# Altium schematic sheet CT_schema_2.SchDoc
size 316 x 185 mm
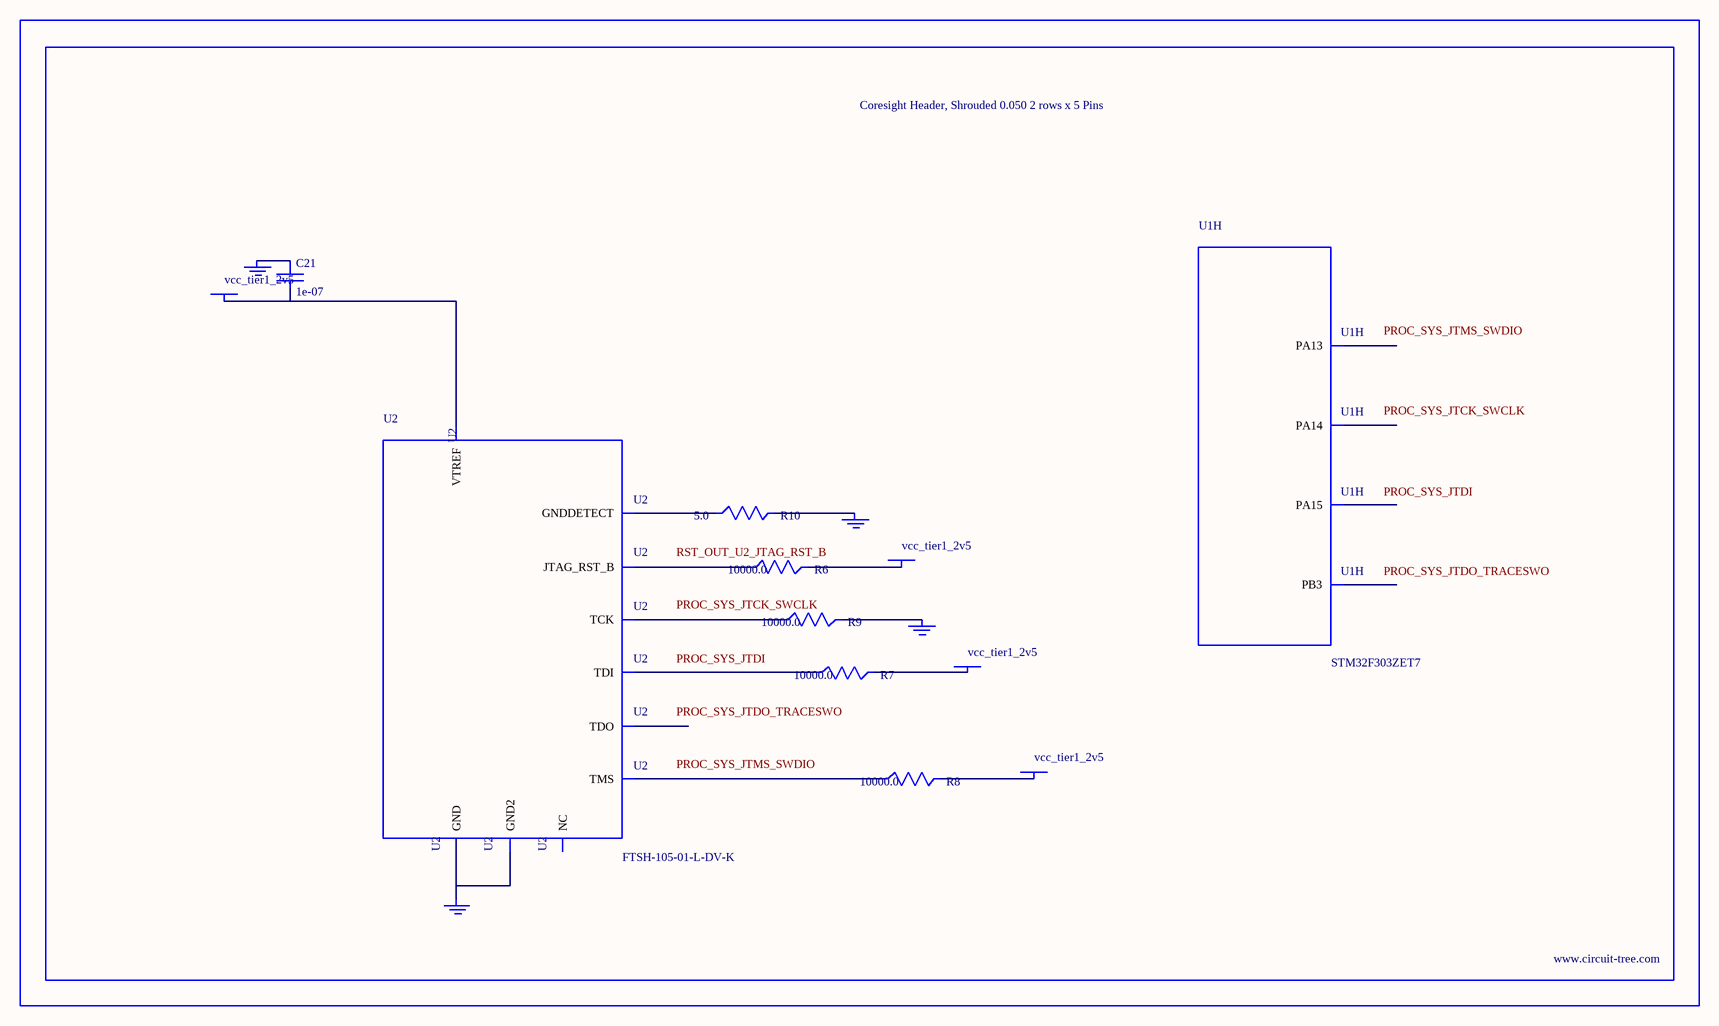
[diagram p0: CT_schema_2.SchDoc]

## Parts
BORDER1  (no value)
C21  1e-07  [C0402]
GND_INSTANCE_1_0  (no value)
GND_INSTANCE_1_1  (no value)
GND_INSTANCE_1_2  (no value)
GND_INSTANCE_1_3  (no value)
POWER_INSTANCE_1_0  vcc_tier1_2v5
POWER_INSTANCE_1_1  vcc_tier1_2v5
POWER_INSTANCE_1_2  vcc_tier1_2v5
POWER_INSTANCE_1_3  vcc_tier1_2v5
R6  10000.0  [R0603]
R7  10000.0  [R0603]
R8  10000.0  [R0603]
R9  10000.0  [R0603]
R10  5.0  [R0603]
U1  STM32F303ZET7  [LQFP144]  (part H of 12)
U2  FTSH-105-01-L-DV-K  [SAMTEC_FTSH-105-01-L-DV-K]

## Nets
NetC21_1: C21.1 GND_INSTANCE_1_0.0(GND)
NetC21_2: C21.2 POWER_INSTANCE_1_0.0(PWR) U2.1(VTREF)
NetGND_INSTANCE_1_1_0: GND_INSTANCE_1_1.0(GND) R9.2
NetGND_INSTANCE_1_2_0: GND_INSTANCE_1_2.0(GND) R10.2
NetGND_INSTANCE_1_3_0: GND_INSTANCE_1_3.0(GND) U2.3(GND) U2.5(GND2)
NetPOWER_INSTANCE_1_1_0: POWER_INSTANCE_1_1.0(PWR) R8.2
NetPOWER_INSTANCE_1_2_0: POWER_INSTANCE_1_2.0(PWR) R7.2
NetPOWER_INSTANCE_1_3_0: POWER_INSTANCE_1_3.0(PWR) R6.2
NetR6_1: R6.1 U2.10(JTAG_RST_B)
NetR7_1: R7.1 U2.8(TDI)
NetR8_1: R8.1 U2.2(TMS)
NetR9_1: R9.1 U2.4(TCK)
NetR10_1: R10.1 U2.9(GNDDETECT)

Not connected (* = marked no-connect by the designer): U1 105(PA13) 109(PA14) 110(PA15) 133(PB3); U2 6(TDO) 7(NC)

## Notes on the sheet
- Labels drawn without touching a wire or pin: PROC_SYS_JTCK_SWCLK, PROC_SYS_JTDI, PROC_SYS_JTDO_TRACESWO, PROC_SYS_JTMS_SWDIO, RST_OUT_U2_JTAG_RST_B

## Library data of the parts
BORDER1 = BORDER_PAGE1
C21 = C0402C104K3RACTU
GND_INSTANCE_1_0-GND_INSTANCE_1_3 = GND
POWER_INSTANCE_1_0-POWER_INSTANCE_1_3 = PWR
R6-R9 = RC0603JR-0710KL
R10 = ERJ-3GEYJ5R1V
